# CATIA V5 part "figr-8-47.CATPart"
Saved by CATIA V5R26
Part number: Part1
Bounding box of the stored display mesh (mm): x -46.99 to 46.99, y -111.421 to 111.421, z 0 to 30
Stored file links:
  D:\_Deepak\CATIA\CATIA V5-6R2016_Deepak\Resources\Part files\Partfiles\c08_catia_v5_6r2016_prt\figr-8-47.CATPart
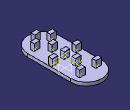
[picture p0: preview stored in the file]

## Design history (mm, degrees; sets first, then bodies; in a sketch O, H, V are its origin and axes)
Body1 (main body)
  Sketch1 on xy-plane, origin (0, 0, 0), H (1, 0, 0), V (0, 1, 0)
    construction line L1 (-46.9897, 64.4313) -> (46.9897, 64.4313)
    line L2 (46.9897, 64.4313) -> (46.9897, -64.4313)
    construction line L3 (46.9897, -64.4313) -> (-46.9897, -64.4313)
    line L4 (-46.9897, -64.4313) -> (-46.9897, 64.4313)
    axis line L5 (46.9897, -64.4313) -> (-46.9897, 64.4313)
    arc A1 centre (0, 64.4313) radius 46.9897 from (-46.9897, 64.4313) to (46.9897, 64.4313) cw
    arc A2 centre (0, -64.4313) radius 46.9897 from (-46.9897, -64.4313) to (46.9897, -64.4313) ccw
    point P7 (0, -111.4211)
    length L3 = 93.9795
    length L2 = 128.8627
    horizontal: L1 H, L3 H
    vertical: L2 V, L4 V
    midpoint: O L5
    tangency: A1 L2, A2 L4
    coincidence: A2 P7, P7 V
  Pad1: profile Sketch1, direction (0, 0, 1), length 10
  Sketch2 on face of Pad1, origin (0, 0, 10), H (1, 0, 0), V (0, 1, 0)
    line L1 (-8.4317, -82.0722) -> (8.3047, -82.0722)
    line L2 (8.3047, -82.0722) -> (8.3047, -93.8638)
    line L3 (8.3047, -93.8638) -> (-8.4317, -93.8638)
    line L4 (-8.4317, -93.8638) -> (-8.4317, -82.0722)
    horizontal: L1 H, L3 H
    vertical: L2 V, L4 V
  Pad2: profile Sketch2, direction (0, 0, 1), length 20
  Sketch3 on face of Pad1, origin (0, 0, 10), H (1, 0, 0), V (0, 1, 0)
    point P1 (-25.1683, -66.0965)
    point P2 (23.8999, -66.0965)
    point P3 (-35.058, 0)
    point P4 (35.3111, 0)
    point P5 (-25.1683, 70.4575)
    point P6 (23.8999, 70.4575)
    point P7 (0, 0)
    point P8 (0, -36.8078)
    point P9 (0, 34.322)
    coincidence: P3 H, P4 H, P7 O, P8 V, P9 V
  UserPattern1: of Pad2, copies 10, at the points of Sketch3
